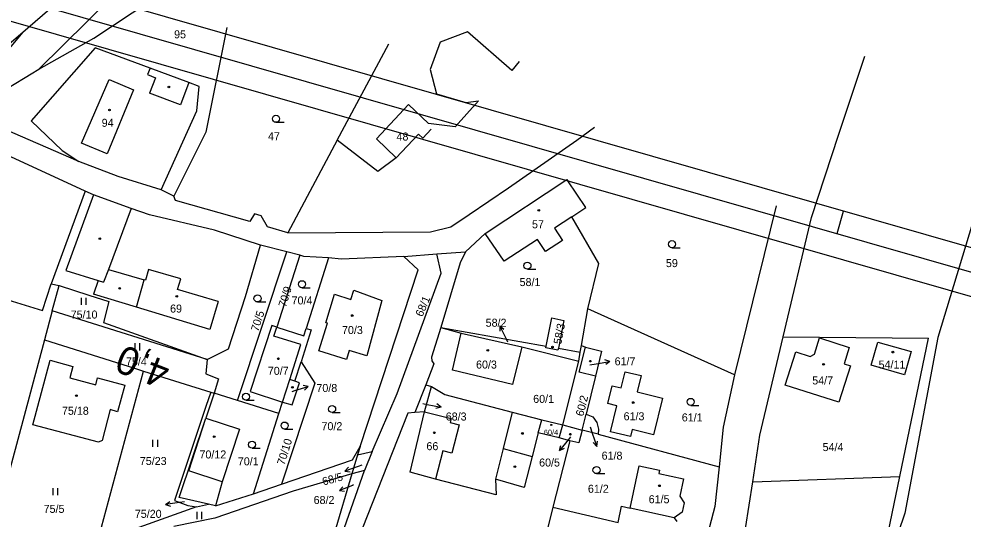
# Model space of a CAD drawing. Extents: x -738085 to -734306, y -1122197 to -1119753.
# Drawn here: x -737103.5 to -736902.9, y -1121438.1 to -1121331.9 of the extents above; entities that cross this region are included whole.
import ezdxf

# ---------------------------------------------------------------- set-up
doc = ezdxf.new("R2010")
doc.units = 0
for name, color, linetype in [('Hranice parcel', 7, 'Continuous'), ('Parcelní čísla', 7, 'Continuous'), ('Pop  PČ popisy', 7, 'Continuous'), ('Vnitřní kresba', 7, 'Continuous'), ('Vrstva 1', 7, 'Continuous'), ('Vrstva 7', 7, 'Continuous'), ('Značky budov', 7, 'Continuous'), ('Značky kultur', 7, 'Continuous')]:
    doc.layers.add(name, color=color, linetype=linetype)

msp = doc.modelspace()

# ---------------------------------------------------------------- linework, layer by layer
at = {"layer": 'Hranice parcel'}
for p, q in [((-737099.21, -1121342.55), (-737053.82, -1121297.62)), ((-737102.67, -1121334.64), (-737095.85, -1121328.77)), ((-737107.06, -1121338.42), (-737102.67, -1121334.64)), ((-737035.85, -1121357.59), (-737024.93, -1121337.17)), ((-737090.71, -1121362.16), (-737114.61, -1121351.76)), ((-737089.4, -1121368.43), (-737111.29, -1121358.42)), ((-737035.85, -1121357.59), (-737046.38, -1121377.27)), ((-737089.4, -1121368.43), (-737096.64, -1121388.08)), ((-737070.55, -1121369.52), (-737073.26, -1121368.17)), ((-736942.64, -1121371.52), (-736951.46, -1121407.39)), ((-737004.43, -1121377.4), (-737008.62, -1121381.28)), ((-737055.33, -1121390.81), (-737052.15, -1121379.91)), ((-737046.55, -1121381.29), (-737052.15, -1121379.91)), ((-737057.01, -1121412.89), (-737046.55, -1121381.29)), ((-737043.83, -1121382.01), (-737046.55, -1121381.29)), ((-737037.72, -1121382.6), (-737042.47, -1121397.55)), ((-737034.97, -1121382.89), (-737037.72, -1121382.6)), ((-737021.68, -1121382.28), (-737034.97, -1121382.89)), ((-737021.68, -1121382.28), (-737014.69, -1121381.74)), ((-737014.69, -1121381.74), (-737008.62, -1121381.28)), ((-737096.64, -1121388.08), (-737094.94, -1121388.43)), ((-737096.39, -1121393.85), (-737094.94, -1121388.43)), ((-737094.94, -1121388.43), (-737088.59, -1121390.48)), ((-737096.39, -1121393.85), (-737098.04, -1121400.02)), ((-737063.46, -1121404.18), (-737096.39, -1121393.85)), ((-736983.97, -1121401.2), (-736982.6, -1121393.38)), ((-736951.46, -1121407.39), (-736982.6, -1121393.38)), ((-736991.5, -1121401.32), (-736990.26, -1121395.35)), ((-736990.26, -1121395.35), (-736987.69, -1121395.87)), ((-736987.69, -1121395.87), (-736988.89, -1121401.78)), ((-737013.86, -1121397.39), (-737009.55, -1121398.56)), ((-737013.86, -1121397.39), (-736991.5, -1121401.32)), ((-737009.55, -1121398.56), (-736996.67, -1121401.46)), ((-737098.04, -1121400.02), (-737111.03, -1121448.36)), ((-736941.12, -1121399.34), (-736910.23, -1121399.65)), ((-736916.35, -1121429.03), (-736910.23, -1121399.65)), ((-736996.67, -1121401.46), (-736984.56, -1121404.54)), ((-736991.57, -1121401.66), (-736991.5, -1121401.32)), ((-736988.98, -1121402.2), (-736991.57, -1121401.66)), ((-736988.89, -1121401.78), (-736988.98, -1121402.2)), ((-736988.89, -1121401.78), (-736984.22, -1121402.6)), ((-736984.56, -1121404.54), (-736984.22, -1121402.6)), ((-736984.22, -1121402.6), (-736983.97, -1121401.2)), ((-736983.97, -1121401.2), (-736983.14, -1121401.52)), ((-737015.34, -1121405.09), (-737017.07, -1121409.52)), ((-736987.97, -1121418.07), (-736984.56, -1121404.54)), ((-737086.41, -1121441.62), (-737077.03, -1121406.61)), ((-737077.03, -1121406.61), (-737062.71, -1121411.1)), ((-737061.07, -1121408.29), (-737062, -1121411.32)), ((-737045.43, -1121413.78), (-737043.87, -1121409.09)), ((-736981.02, -1121407.7), (-736982.98, -1121415.74)), ((-737062.71, -1121411.1), (-737063.74, -1121414.16)), ((-737062.71, -1121411.1), (-737062, -1121411.32)), ((-737054.36, -1121410.93), (-737047.45, -1121413.21)), ((-737017.07, -1121409.52), (-737019.38, -1121415.42)), ((-737017.29, -1121415.25), (-737015.81, -1121409.87)), ((-737017.07, -1121409.52), (-737015.81, -1121409.87)), ((-737062.46, -1121412.77), (-737063.77, -1121416.64)), ((-737062, -1121411.32), (-737062.46, -1121412.77)), ((-737057.01, -1121412.89), (-737062, -1121411.32)), ((-737048.23, -1121415.65), (-737057.01, -1121412.89)), ((-737048.23, -1121415.65), (-737047.45, -1121413.21)), ((-737047.45, -1121413.21), (-737045.43, -1121413.78)), ((-737053.64, -1121432.68), (-737048.23, -1121415.65)), ((-737019.38, -1121415.42), (-737020.84, -1121415.54)), ((-737017.29, -1121415.25), (-737019.38, -1121415.42)), ((-736993.14, -1121419.7), (-736992.37, -1121416.94)), ((-736992.37, -1121416.94), (-736987.97, -1121418.07)), ((-736983.81, -1121419.14), (-736982.98, -1121415.74)), ((-736988.73, -1121420.82), (-736987.97, -1121418.07)), ((-736987.97, -1121418.07), (-736983.81, -1121419.14)), ((-736980.41, -1121420.01), (-736983.81, -1121419.14)), ((-736988.73, -1121420.82), (-736993.14, -1121419.7)), ((-736986.43, -1121421.4), (-736988.73, -1121420.82)), ((-736980.41, -1121420.01), (-736954.76, -1121426.92)), ((-737032.63, -1121425.46), (-737031, -1121422.65)), ((-737031, -1121422.65), (-737031.52, -1121424.42)), ((-736986.43, -1121421.4), (-736990.06, -1121435.51)), ((-737031.52, -1121424.42), (-737032.72, -1121428.47)), ((-737031.52, -1121424.42), (-737028.45, -1121423.71)), ((-737028.45, -1121423.71), (-737030.09, -1121427.7)), ((-737047.66, -1121430.62), (-737032.63, -1121425.46)), ((-736954.76, -1121426.92), (-736955.65, -1121435.39)), ((-737040.2, -1121456.84), (-737030.09, -1121427.7)), ((-737030.09, -1121427.7), (-737032.72, -1121428.47)), ((-736947.61, -1121430.12), (-736916.35, -1121429.03)), ((-736922.28, -1121457.48), (-736916.35, -1121429.03)), ((-737053.64, -1121432.68), (-737047.66, -1121430.62)), ((-737061.74, -1121435.21), (-737053.64, -1121432.68)), ((-737065.76, -1121435.46), (-737063.21, -1121434.87)), ((-737061.74, -1121435.21), (-737063.21, -1121434.87)), ((-737065.76, -1121435.46), (-737080.78, -1121440.8)), ((-736990.06, -1121435.51), (-736994.34, -1121452.82)), ((-736990.06, -1121435.51), (-736976.21, -1121438.75)), ((-736976.21, -1121438.75), (-736975.46, -1121435.33)), ((-736955.65, -1121435.39), (-736957.67, -1121443.08))]:
    msp.add_line(p, q, dxfattribs=at)
for points in [[(-737099.21, -1121342.55), (-737087.58, -1121335.98), (-737075.43, -1121327.97), (-737063, -1121313.38), (-737055.74, -1121304.46)], [(-737102.67, -1121334.64), (-737110.98, -1121344.57), (-737118.85, -1121349.91)], [(-737059.3, -1121333.65), (-737063.76, -1121355.87), (-737070.55, -1121369.52)], [(-736997.19, -1121340.89), (-736998.74, -1121342.78), (-737008.22, -1121334.61), (-737014.02, -1121336.8), (-737016.11, -1121342.59), (-737014.75, -1121347.77), (-737008.54, -1121349.59), (-737005.82, -1121349.25), (-737010.84, -1121354.74), (-737016.44, -1121354.08), (-737020.69, -1121350.05), (-737027.51, -1121357.32), (-737023.34, -1121361.35), (-737027.22, -1121364.26), (-737035.85, -1121357.59)], [(-737073.26, -1121368.17), (-737065.69, -1121351.4), (-737065.19, -1121346.18), (-737067.35, -1121345.38), (-737075.62, -1121342.32), (-737087.27, -1121338), (-737100.86, -1121353.47), (-737094.31, -1121359.76), (-737090.71, -1121362.16)], [(-736941.12, -1121399.34), (-736935.13, -1121374.04), (-736929.37, -1121356.56), (-736923.82, -1121339.74)], [(-736894.23, -1121340.75), (-736890.46, -1121340.68), (-736908.31, -1121399.47), (-736915.28, -1121436.76), (-736922.28, -1121457.48)], [(-737114.61, -1121351.76), (-737110.73, -1121349.44), (-737099.21, -1121342.55)], [(-737046.38, -1121377.27), (-737016.02, -1121377.03), (-737011.74, -1121376), (-737007.85, -1121373.41), (-736999.49, -1121367.7), (-736984.97, -1121357.57), (-736981.21, -1121354.84)], [(-737073.26, -1121368.17), (-737082.42, -1121365.32), (-737090.71, -1121362.16)], [(-737004.43, -1121377.4), (-736987.09, -1121365.95), (-736986.88, -1121366.26)], [(-736986.02, -1121373.86), (-736983.04, -1121371.9), (-736986.88, -1121366.26)], [(-737052.15, -1121379.91), (-737061.94, -1121376.73), (-737075.76, -1121373.47), (-737079.62, -1121372.09), (-737087.61, -1121369.23), (-737089.4, -1121368.43)], [(-737046.38, -1121377.27), (-737050.66, -1121375.99), (-737052.04, -1121373.7), (-737053.46, -1121373.26), (-737054.4, -1121374.84), (-737070.21, -1121370.4), (-737070.55, -1121369.52)], [(-736986.02, -1121373.86), (-736989.72, -1121376.29), (-736988, -1121378.93), (-736991.63, -1121381.27), (-736993.35, -1121378.67), (-737000.4, -1121383.3), (-737004.43, -1121377.4)], [(-736982.6, -1121393.38), (-736980.29, -1121383.75), (-736986.02, -1121373.86)], [(-737043.83, -1121382.01), (-737045.51, -1121387.3), (-737048.68, -1121397.27)], [(-737037.72, -1121382.6), (-737042.95, -1121382.27), (-737043.83, -1121382.01)], [(-737031, -1121422.65), (-737018.68, -1121385.12), (-737021.68, -1121382.28)], [(-737028.45, -1121423.71), (-737023.15, -1121411.41), (-737013.79, -1121385.83), (-737014.69, -1121381.74)], [(-737008.62, -1121381.28), (-737009.73, -1121383.65), (-737013.86, -1121397.39)], [(-737125.2, -1121385.57), (-737098.43, -1121393.73), (-737096.64, -1121388.08)], [(-737088.59, -1121390.48), (-737084.36, -1121391.88), (-737085.5, -1121396.32), (-737063.46, -1121404.18)], [(-737063.46, -1121404.18), (-737058.92, -1121401.93), (-737055.33, -1121390.81)], [(-737032.35, -1121389.47), (-737026.35, -1121391.67), (-737029.56, -1121403.4), (-737033.31, -1121402.26), (-737033.89, -1121404.14), (-737039.74, -1121402.35), (-737037.94, -1121396.46), (-737038.28, -1121396.36), (-737036.44, -1121390.33), (-737032.94, -1121391.4), (-737032.35, -1121389.47)], [(-737048.68, -1121397.27), (-737049.72, -1121396.92), (-737054.36, -1121410.93)], [(-737047.45, -1121413.21), (-737045.93, -1121408.41), (-737043.57, -1121401.01), (-737049.29, -1121399.19), (-737048.68, -1121397.27)], [(-737048.68, -1121397.27), (-737042.98, -1121399.16), (-737042.47, -1121397.55)], [(-737042.47, -1121397.55), (-737041.39, -1121397.89), (-737043.55, -1121404.67)], [(-737013.86, -1121397.39), (-737015.86, -1121403.66), (-737015.76, -1121404.48), (-737015.34, -1121405.09)], [(-736996.67, -1121401.46), (-736998.6, -1121409.5), (-737011.38, -1121406.41), (-737009.55, -1121398.56)], [(-737098.04, -1121400.02), (-737078.94, -1121406.01), (-737077.03, -1121406.61)], [(-736947.61, -1121430.12), (-736946.07, -1121420.2), (-736941.12, -1121399.34)], [(-736927.13, -1121401.63), (-736928.21, -1121405.06), (-736926.85, -1121405.49), (-736929.28, -1121413.24), (-736940.69, -1121409.64), (-736938.43, -1121402.54), (-736935.4, -1121403.5), (-736934.47, -1121403.02), (-736933.4, -1121399.6), (-736927.13, -1121401.63)], [(-736920.99, -1121400.5), (-736913.92, -1121402.47), (-736915.35, -1121407.4), (-736922.43, -1121405.38), (-736920.99, -1121400.5)], [(-736981.02, -1121407.7), (-736984.46, -1121406.89), (-736983.14, -1121401.52)], [(-736983.14, -1121401.52), (-736979.7, -1121402.38), (-736981.02, -1121407.7)], [(-737096.84, -1121404.33), (-737092.05, -1121405.62), (-737092.64, -1121408.03), (-737087.11, -1121409.51), (-737086.76, -1121408.07), (-737081, -1121409.6), (-737082.51, -1121415.25), (-737084.07, -1121414.81), (-737085.8, -1121421.33), (-737086.53, -1121421.75), (-737100.48, -1121418.04), (-737096.84, -1121404.33)], [(-737063.46, -1121404.18), (-737063.74, -1121407.21), (-737061.07, -1121408.29)], [(-737043.55, -1121404.67), (-737040.6, -1121409.22), (-737047.66, -1121430.62)], [(-737043.87, -1121409.09), (-737044.85, -1121408.76), (-737043.55, -1121404.67)], [(-736976.44, -1121413.98), (-736978.37, -1121413.5), (-736977.45, -1121409.74), (-736975.52, -1121410.21), (-736974.67, -1121406.75), (-736971.32, -1121407.57), (-736972.12, -1121411.05), (-736966.78, -1121412.36), (-736968.7, -1121420.14), (-736973.23, -1121419.02), (-736973.59, -1121420.53), (-736977.79, -1121419.5), (-736976.44, -1121413.98)], [(-736951.46, -1121407.39), (-736953.88, -1121418.56), (-736954.76, -1121426.92)], [(-737015.81, -1121409.87), (-737012.99, -1121411.6), (-736998.68, -1121415.33), (-736992.37, -1121416.94)], [(-737063.74, -1121414.16), (-737070.39, -1121434.09), (-737067.57, -1121435.18), (-737065.76, -1121435.46)], [(-737063.21, -1121434.87), (-737069.46, -1121433.45), (-737063.77, -1121416.64)], [(-737063.77, -1121416.64), (-737056.59, -1121418.99), (-737060.27, -1121430.12), (-737061.74, -1121435.21)], [(-737020.84, -1121415.54), (-737030.57, -1121440.13), (-737031.78, -1121443.99), (-737037.57, -1121467.69), (-737037.83, -1121474.89)], [(-736993.14, -1121419.7), (-736994.46, -1121424.76), (-736996.18, -1121431.31), (-737002.27, -1121429.58), (-737002.11, -1121432.93), (-737014.95, -1121429.58), (-737020.38, -1121428.11), (-737017.29, -1121415.25)], [(-736982.98, -1121415.74), (-736981.57, -1121416.37), (-736980.68, -1121417.52), (-736980.33, -1121418.95), (-736980.41, -1121420.01)], [(-736983.81, -1121419.14), (-736984.51, -1121421.89), (-736986.43, -1121421.4)], [(-736975.46, -1121435.33), (-736973.66, -1121435.75), (-736971.75, -1121426.71), (-736967.37, -1121427.64), (-736967.53, -1121428.4), (-736962.3, -1121429.52), (-736963.08, -1121433.17), (-736962.18, -1121434.63), (-736962.58, -1121436.6), (-736964.29, -1121437.75), (-736963.73, -1121438.53)], [(-737032.72, -1121428.47), (-737045.19, -1121432.11), (-737061.83, -1121437.82), (-737070.54, -1121439.64)], [(-737032.72, -1121428.47), (-737036.48, -1121441.18), (-737040.2, -1121456.84)], [(-736951.39, -1121450.42), (-736949.93, -1121445), (-736947.61, -1121430.12)]]:
    msp.add_lwpolyline(points, dxfattribs=at)
at = {"layer": 'Pop  PČ popisy'}
for p, q in [((-736999.99, -1121399.71), (-737001.35, -1121397.04)), ((-737001.35, -1121397.04), (-737000.45, -1121397.7)), ((-737001.35, -1121397.04), (-737001.34, -1121398.16)), ((-736999.6, -1121400.48), (-736999.99, -1121399.71)), ((-736982.2, -1121405.32), (-736980.89, -1121405.08)), ((-736980.89, -1121405.08), (-736977.94, -1121404.56)), ((-736977.94, -1121404.56), (-736979.01, -1121404.24)), ((-736977.94, -1121404.56), (-736978.83, -1121405.23)), ((-737045.45, -1121410.94), (-737044.89, -1121410.77)), ((-737044.89, -1121410.77), (-737042.02, -1121409.89)), ((-737042.02, -1121409.89), (-737043.12, -1121409.71)), ((-737042.02, -1121409.89), (-737042.83, -1121410.66)), ((-737017.68, -1121413.51), (-737016.75, -1121413.7)), ((-737016.75, -1121413.7), (-737013.8, -1121414.27)), ((-737013.8, -1121414.27), (-737014.88, -1121414.57)), ((-737013.8, -1121414.27), (-737014.69, -1121413.59)), ((-736982.14, -1121418.47), (-736981.69, -1121419.77)), ((-736986.76, -1121421.12), (-736988.61, -1121423.49)), ((-736986.34, -1121420.59), (-736986.76, -1121421.12)), ((-736981.69, -1121419.77), (-736980.71, -1121422.61)), ((-736988.61, -1121423.49), (-736988.39, -1121422.39)), ((-736988.61, -1121423.49), (-736987.6, -1121423)), ((-736980.71, -1121422.61), (-736981.51, -1121421.82)), ((-736980.71, -1121422.61), (-736980.57, -1121421.5)), ((-737031.4, -1121426.86), (-737034.24, -1121427.84)), ((-737034.24, -1121427.84), (-737033.45, -1121427.04)), ((-737030.64, -1121426.61), (-737031.4, -1121426.86)), ((-737034.24, -1121427.84), (-737033.13, -1121427.98)), ((-737032.61, -1121430.89), (-737035.39, -1121432.01)), ((-737035.39, -1121432.01), (-737034.65, -1121431.18)), ((-737032.37, -1121430.8), (-737032.61, -1121430.89)), ((-737035.39, -1121432.01), (-737034.28, -1121432.1)), ((-737072.3, -1121434.93), (-737071.38, -1121434.29)), ((-737069.33, -1121434.51), (-737072.3, -1121434.93)), ((-737072.3, -1121434.93), (-737071.24, -1121435.28)), ((-737068.27, -1121434.35), (-737069.33, -1121434.51))]:
    msp.add_line(p, q, dxfattribs=at)
at = {"layer": 'Vnitřní kresba'}
for p, q in [((-737075.62, -1121342.32), (-737076.15, -1121343.67)), ((-737090.16, -1121358.25), (-737084.32, -1121344.7)), ((-737084.32, -1121344.7), (-737079.15, -1121346.94)), ((-737076.15, -1121343.67), (-737074.48, -1121344.36)), ((-737074.48, -1121344.36), (-737075.7, -1121347.59)), ((-737079.15, -1121346.94), (-737084.71, -1121360.52)), ((-737067.35, -1121345.38), (-737069.18, -1121350.08)), ((-737069.18, -1121350.08), (-737075.7, -1121347.59)), ((-737023.34, -1121361.35), (-737018.59, -1121356.35)), ((-737018.59, -1121356.35), (-737017.69, -1121357.2)), ((-737017.69, -1121357.2), (-737015.87, -1121355.28)), ((-737084.71, -1121360.52), (-737090.16, -1121358.25)), ((-737087.61, -1121369.23), (-737093.47, -1121385.25)), ((-737079.62, -1121372.09), (-737084.47, -1121385.03)), ((-737084.47, -1121385.03), (-737085.49, -1121387.76)), ((-737084.47, -1121385.03), (-737076.84, -1121387.26)), ((-737093.47, -1121385.25), (-737086.64, -1121387.4)), ((-737075.92, -1121385.07), (-737076.58, -1121387.34)), ((-737069.09, -1121387.07), (-737075.92, -1121385.07)), ((-737086.64, -1121387.4), (-737087.6, -1121390.29)), ((-737086.64, -1121387.4), (-737085.49, -1121387.76)), ((-737078.48, -1121393.05), (-737076.84, -1121387.26)), ((-737076.58, -1121387.34), (-737076.84, -1121387.26)), ((-737069.75, -1121389.34), (-737069.09, -1121387.07)), ((-737078.48, -1121393.05), (-737087.6, -1121390.29)), ((-737061.16, -1121391.85), (-737069.75, -1121389.34)), ((-737062.89, -1121397.77), (-737078.48, -1121393.05)), ((-737061.16, -1121391.85), (-737062.89, -1121397.77)), ((-737044.85, -1121408.76), (-737045.93, -1121408.41)), ((-737067.4, -1121427.8), (-737063.77, -1121416.64)), ((-737017.29, -1121415.25), (-737011.67, -1121416.68)), ((-737011.67, -1121416.68), (-737011.89, -1121417.56)), ((-736998.68, -1121415.33), (-737000.63, -1121423.06)), ((-737011.89, -1121417.56), (-737009.98, -1121418.04)), ((-737009.98, -1121418.04), (-737011.51, -1121424.06)), ((-737000.63, -1121423.06), (-737002.27, -1121429.58)), ((-737000.63, -1121423.06), (-736994.46, -1121424.76)), ((-737013.42, -1121423.58), (-737014.95, -1121429.58)), ((-737011.51, -1121424.06), (-737013.42, -1121423.58)), ((-737060.27, -1121430.12), (-737067.4, -1121427.8)), ((-736964.29, -1121437.75), (-736973.66, -1121435.75))]:
    msp.add_line(p, q, dxfattribs=at)
at = {"layer": 'Vrstva 1'}
msp.add_line((-736929.67, -1121377.44), (-736928.3, -1121372.64), dxfattribs=at)
for points in [[(-736726.43, -1121430.48), (-737533.93, -1121199.12), (-737615.73, -1121484.62), (-736808.23, -1121715.98)], [(-737530.5, -1121205.3), (-736732.61, -1121433.9), (-736811.65, -1121709.79), (-737609.54, -1121481.19)], [(-736738.79, -1121437.33), (-737330, -1121267.94), (-737406.29, -1121534.23), (-736815.08, -1121703.62)]]:
    msp.add_lwpolyline(points, close=True, dxfattribs=at)
at = {"layer": 'Značky budov'}
for centre, radius in [((-737071.61, -1121346.3), 0.175), ((-737084.23, -1121351.19), 0.175), ((-736993.05, -1121372.49), 0.175), ((-737086.28, -1121378.51), 0.175), ((-737082.06, -1121389.07), 0.175), ((-737069.93, -1121390.74), 0.175), ((-737032.67, -1121394.84), 0.175), ((-737003.87, -1121402.23), 0.175), ((-736990.13, -1121401.53), 0.175), ((-736917.83, -1121402.6), 0.175), ((-737048.35, -1121404.01), 0.175), ((-736982.11, -1121404.52), 0.175), ((-736932.55, -1121405.19), 0.175), ((-737045.37, -1121410.09), 0.175), ((-737091.25, -1121411.83), 0.175), ((-736972.99, -1121413.31), 0.175), ((-736990.38, -1121418.05), 0.117), ((-737061.98, -1121420.54), 0.175), ((-737015.24, -1121419.72), 0.175), ((-736996.52, -1121419.86), 0.175), ((-736986.33, -1121420.03), 0.175), ((-736998.12, -1121426.93), 0.175), ((-736967.41, -1121430.98), 0.175)]:
    msp.add_circle(centre, radius, dxfattribs=at)
at = {"layer": 'Značky kultur'}
for p, q in [((-737048.87, -1121353.81), (-737047.12, -1121353.81)), ((-736964.75, -1121380.43), (-736963, -1121380.43)), ((-736995.45, -1121385), (-736993.7, -1121385)), ((-737043.34, -1121388.94), (-737041.59, -1121388.94)), ((-737090.15, -1121392.59), (-737090.15, -1121391.09)), ((-737089.15, -1121392.59), (-737089.15, -1121391.09)), ((-737052.79, -1121391.95), (-737051.04, -1121391.95)), ((-737078.76, -1121402.23), (-737078.76, -1121400.73)), ((-737077.76, -1121402.23), (-737077.76, -1121400.73)), ((-737055.24, -1121412.81), (-737053.49, -1121412.81)), ((-736960.78, -1121413.92), (-736959.03, -1121413.92)), ((-737036.95, -1121415.44), (-737035.2, -1121415.44)), ((-737047.03, -1121418.94), (-737045.28, -1121418.94)), ((-737074.99, -1121422.69), (-737074.99, -1121421.19)), ((-737073.99, -1121422.69), (-737073.99, -1121421.19)), ((-737053.95, -1121422.99), (-737052.2, -1121422.99)), ((-736980.78, -1121428.4), (-736979.03, -1121428.4)), ((-737096.2, -1121432.95), (-737096.2, -1121431.45)), ((-737095.2, -1121432.95), (-737095.2, -1121431.45)), ((-737065.63, -1121438.03), (-737065.63, -1121436.53)), ((-737064.63, -1121438.03), (-737064.63, -1121436.53))]:
    msp.add_line(p, q, dxfattribs=at)
for centre in [(-737048.87, -1121353.06), (-736964.75, -1121379.68), (-736995.45, -1121384.25), (-737043.34, -1121388.19), (-737052.79, -1121391.2), (-737055.24, -1121412.06), (-736960.78, -1121413.17), (-737036.95, -1121414.69), (-737047.03, -1121418.19), (-737053.95, -1121422.24), (-736980.78, -1121427.65)]:
    msp.add_circle(centre, 0.75, dxfattribs=at)

# ---------------------------------------------------------------- texts
at = {"layer": 'Parcelní čísla'}
for s, height, p in [('95', 1.7, (-737070.51, -1121335.98)), ('94', 1.7, (-737085.89, -1121354.76)), ('47', 1.7, (-737050.57, -1121357.63)), ('48', 1.7, (-737023.26, -1121357.68)), ('57', 1.7, (-736994.48, -1121376.31)), ('59', 1.7, (-736966.04, -1121384.55)), ('58/1', 1.7, (-736997.12, -1121388.58)), ('70/4', 1.7, (-737045.55, -1121392.47)), ('69', 1.7, (-737071.36, -1121394.2)), ('75/10', 1.7, (-737092.47, -1121395.47)), ('70/3', 1.7, (-737034.84, -1121398.76)), ('58/2', 1.7, (-737004.33, -1121397.21)), ('75/4', 1.7, (-737080.73, -1121405.43)), ('60/3', 1.7, (-737006.37, -1121406.09)), ('61/7', 1.7, (-736976.94, -1121405.4)), ('54/11', 1.7, (-736920.86, -1121406.09)), ('70/7', 1.7, (-737050.6, -1121407.42)), ('54/7', 1.7, (-736934.96, -1121409.46)), ('70/8', 1.7, (-737040.28, -1121411.06)), ('60/1', 1.7, (-736994.23, -1121413.38)), ('75/18', 1.7, (-737094.32, -1121415.9)), ('68/3', 1.7, (-737012.81, -1121417.12)), ('61/3', 1.7, (-736975.03, -1121417.07)), ('61/1', 1.7, (-736962.67, -1121417.31)), ('70/2', 1.7, (-737039.2, -1121419.17)), ('60/4', 1.14, (-736991.98, -1121420.21)), ('66', 1.7, (-737016.91, -1121423.42)), ('54/4', 1.7, (-736932.76, -1121423.61)), ('75/23', 1.7, (-737077.79, -1121426.56)), ('70/12', 1.7, (-737065.12, -1121425.17)), ('70/1', 1.7, (-737056.97, -1121426.63)), ('60/5', 1.7, (-736992.97, -1121426.89)), ('61/8', 1.7, (-736979.7, -1121425.43)), ('61/2', 1.7, (-736982.61, -1121432.46)), ('68/2', 1.7, (-737040.87, -1121434.84)), ('61/5', 1.7, (-736969.7, -1121434.68)), ('75/5', 1.7, (-737098.22, -1121436.73)), ('75/20', 1.7, (-737078.85, -1121437.78))]:
    msp.add_text(s, height=height, dxfattribs=at).set_placement(p)
for s, rotation, p in [('70/9', 73, (-737046.77, -1121393.19)), ('68/1', 67, (-737017.77, -1121395.22)), ('70/5', 72, (-737052.64, -1121398.35)), ('58/3', 79, (-736988.29, -1121401.04)), ('60/2', 76, (-736983.6, -1121416.33)), ('70/10', 73, (-737047.07, -1121426.71)), ('68/5', 15, (-737038.78, -1121430.93))]:
    msp.add_text(s, height=1.7, rotation=rotation, dxfattribs=at).set_placement(p)
at = {"layer": 'Vrstva 7'}
msp.add_text('4,0', height=6, rotation=158.5969, dxfattribs=at).set_placement((-737070.91, -1121404.97))

doc.saveas('drawing.dxf')
